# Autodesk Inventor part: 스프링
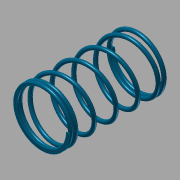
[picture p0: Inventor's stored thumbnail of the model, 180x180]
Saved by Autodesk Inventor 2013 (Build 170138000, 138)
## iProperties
Created: 2019-02
Part Number: 스프링
Material: 강철
Document SubType Name: Modeling
Designer: mduedu
Density: 2.18 g/cm^3
CustomPartVersion: 1
Author: mduedu
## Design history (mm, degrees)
sketch "경로 단면 스케치(오른쪽)"
  geometry: L1 (-7, 0.125)-(-7, -0.125); L2 (-19.793, 0)-(-17.307, 0) reference; L3 (0, -1.242)-(0, 1.242) reference; 1 further point
  constraints: 2 end point, 1 midpoint, 1 point on line, 1 vertical
  dimensions: "d0" = 0.25 distance of L1.start L1.end (= 0.25 x da_d); "d278" = 14 diameter of L1 L3 (derived)
feature "기본 곡선(오른쪽)" sketch "경로 단면 스케치(오른쪽)" dims "d2" = 5.79943 (= da_ti), "d3" = 10, "d4" = 32.5 (derived), "d5" = 0, "d6" = 90 deg, "d7" = 90 deg, "d8" = 0, "d9" = 0
sketch "주 코일 경로(오른쪽)"
node "단면 작업 평면(오른쪽)"
node "시작 작업 평면(오른쪽)"
node "끝 작업 평면(오른쪽)"
node "끝 절단 작업 평면(오른쪽)"
node "시작 절단 작업 평면(오른쪽)"
node "평면 끝 절단 작업 평면 1(오른쪽)"
node "평면 끝 절단 작업 평면 2(오른쪽)"
sketch "코일 단면 스케치(오른쪽)"
  geometry: C1 r 0.5 at (0, 0); 1 further point
  constraints: 1 centre point, 1 coincident
  dimensions: "d14" = 1 diameter of C1 (= da_d)
feature "Main Coil Feature(R)" sketch "코일 단면 스케치(오른쪽)" dims "d15" = 0, "d102" = 0 (computed from const_zero), "da_rightdir" = 10 [user parameter; used in 1 equation term]
sketch "시작 변이 코일 스케치 1(오른쪽)"
  geometry: 2 further points
  constraints: 1 horizontal alignment
feature "시작 변이 코일 1(오른쪽)" sketch "시작 변이 코일 스케치 1(오른쪽)" pitch "d16" = 4.59957 (derived); turns "d18" = 0.25 (derived); dims "d17" = 10, "d19" = 0, angle "d20" = 90 deg, angle "d21" = 90 deg, "d22" = 0, "d23" = 0, "d103" = 0 (derived), "const_zero" = 0 [user parameter; used in 2 equation terms]
sketch "Sketch  Start Transition 2(R)"
  geometry: 2 further points
  constraints: 1 horizontal alignment
feature "Coil  Start Transition 2(R)" sketch "Sketch  Start Transition 2(R)" pitch "d24" = 3.39971 (derived); turns "d26" = 0.25 (derived); dims "d25" = 10, "d27" = 0, angle "d28" = 90 deg, angle "d29" = 90 deg, "d30" = 0, "d31" = 0, "d114" = 0 (derived), "const_zero" = 0 [user parameter; used in 2 equation terms]
sketch "Sketch  Start Transition 3(R)"
  geometry: 2 further points
  constraints: 1 horizontal alignment
feature "Coil  Start Transition 3(R)" sketch "Sketch  Start Transition 3(R)" pitch "d32" = 2.19986 (derived); turns "d34" = 0.25 (derived); dims "d33" = 10, "d35" = 0, angle "d36" = 90 deg, angle "d37" = 90 deg, "d38" = 0, "d39" = 0, "d104" = 0 (derived), "const_zero" = 0 [user parameter; used in 2 equation terms]
sketch "Sketch  Start Transition 4(R)"
  geometry: 2 further points
  constraints: 1 horizontal alignment
feature "Coil  Start Transition 4(R)" sketch "Sketch  Start Transition 4(R)" pitch "d40" = 1 (derived); turns "d42" = 0.25 (derived); dims "d41" = 10, "d43" = 0, angle "d44" = 90 deg, angle "d45" = 90 deg, "d46" = 0, "d47" = 0, "d105" = 0 (derived), "const_zero" = 0 [user parameter; used in 2 equation terms]
sketch "시작 끝 스케치(오른쪽)"
  geometry: 2 further points
  constraints: 1 horizontal alignment
feature "시작 끝 코일(오른쪽)" sketch "시작 끝 스케치(오른쪽)" turns "d82" = 1.5 (derived); pitch "End_Pitch" = 1.00866 (computed from da_d, spiral_Angle); dims "d81" = 10, "d83" = 0, angle "d84" = 90 deg, angle "d85" = 90 deg, "d86" = 0, "d87" = 0, "d106" = 0 (derived), "const_zero" = 0 [user parameter; used in 2 equation terms]
sketch "시작 절단 스케치(오른쪽)"
  geometry: L1 (-14.5, -7.5)-(0.5, -7.5); L2 (0.5, -7.5)-(0.5, 7.5); L3 (0.5, 7.5)-(-14.5, 7.5); L4 (-14.5, 7.5)-(-14.5, -7.5); L5 (12.39, 0)-(-49.49, 0) reference; L6 (-7, -30.94)-(-7, 30.94) reference; 2 further points
  constraints: 8 end point, 2 midpoint, 2 parallel, 2 perpendicular, 2 point on line, 1 horizontal
  dimensions: "d99" = 15 distance of L1.start L1.end (= da_D2 + 2 x da_d)
extrude "시작 절단 피쳐(오른쪽)" cut sketch "시작 절단 스케치(오른쪽)" stored distance "d100" = 1.00866 (derived); taper "d101" = 0 deg; dims "d131" = 0 (derived), "const_zero" = 0 [user parameter; used in 2 equation terms]
sketch "끝 변이 코일 스케치 1(오른쪽)"
  geometry: 2 further points
  constraints: 1 horizontal alignment
feature "끝 변이 코일 1(오른쪽)" sketch "끝 변이 코일 스케치 1(오른쪽)" pitch "d48" = 4.59957 (derived); turns "d50" = 0.1875 (derived); dims "d49" = 10, "d51" = 0, angle "d52" = 90 deg, angle "d53" = 90 deg, "d54" = 0, "d55" = 0, "d108" = 0 (derived), "const_zero" = 0 [user parameter; used in 2 equation terms]
sketch "끝 변이 코일 스케치 2(오른쪽)"
  geometry: 2 further points
  constraints: 1 horizontal alignment
feature "끝 변이 코일 2(오른쪽)" sketch "끝 변이 코일 스케치 2(오른쪽)" pitch "d56" = 3.39971 (derived); turns "d58" = 0.1875 (derived); dims "d57" = 10, "d59" = 0, angle "d60" = 90 deg, angle "d61" = 90 deg, "d62" = 0, "d63" = 0, "d132" = 0 (derived), "const_zero" = 0 [user parameter; used in 2 equation terms]
sketch "끝 변이 코일 스케치 3(오른쪽)"
  geometry: 2 further points
  constraints: 1 horizontal alignment
feature "끝 변이 코일 3(오른쪽)" sketch "끝 변이 코일 스케치 3(오른쪽)" pitch "d64" = 2.19986 (derived); turns "d66" = 0.1875 (derived); dims "d65" = 10, "d67" = 0, angle "d68" = 90 deg, angle "d69" = 90 deg, "d70" = 0, "d71" = 0, "d133" = 0 (derived), "const_zero" = 0 [user parameter; used in 2 equation terms]
sketch "끝 변이 코일 스케치 4(오른쪽)"
  geometry: 2 further points
  constraints: 1 horizontal alignment
feature "끝 변이 코일 4(오른쪽)" sketch "끝 변이 코일 스케치 4(오른쪽)" pitch "d72" = 1 (derived); turns "d74" = 0.1875 (derived); dims "d73" = 10, "d75" = 0, angle "d76" = 90 deg, angle "d77" = 90 deg, "d78" = 0, "d79" = 0, "d134" = 0 (derived), "const_zero" = 0 [user parameter; used in 2 equation terms]
sketch "끝 코일 스케치(오른쪽)"
  geometry: 2 further points
  constraints: 1 horizontal alignment
feature "끝 코일(오른쪽)" sketch "끝 코일 스케치(오른쪽)" pitch "d88" = 1.00866 (= End_Pitch); turns "d90" = 1 (derived); dims "d89" = 10, "d91" = 0, angle "d92" = 90 deg, angle "d93" = 90 deg, "d94" = 0, "d95" = 0, "d112" = 0 (derived), "const_zero" = 0 [user parameter; used in 2 equation terms]
sketch "끝 절단 스케치(오른쪽)"
  geometry: L1 (-7.5, 0.5)-(7.5, 0.5); L2 (7.5, 0.5)-(7.5, -14.5); L3 (7.5, -14.5)-(-7.5, -14.5); L4 (-7.5, -14.5)-(-7.5, 0.5); L5 (30.94, -7)-(-30.94, -7) reference; L6 (0, -49.49)-(0, 12.39) reference; 2 further points
  constraints: 8 end point, 2 midpoint, 2 parallel, 2 perpendicular, 2 point on line, 1 horizontal
  dimensions: "d96" = 15 distance of L1.start L1.end (= da_D2 + 2 x da_d)
extrude "끝 절단 피쳐(오른쪽)" cut sketch "끝 절단 스케치(오른쪽)" stored distance "d97" = 1.00866 (derived); taper "d98" = 0 deg; dims "d113" = 0 (derived), "const_zero" = 0 [user parameter; used in 2 equation terms]
sketch "평면 끝 절단 스케치 1(오른쪽)"
  geometry: L1 (0.5, -7.5)-(-14.5, -7.5); L2 (-14.5, -7.5)-(-14.5, 7.5); L3 (-14.5, 7.5)-(0.5, 7.5); L4 (0.5, 7.5)-(0.5, -7.5); L5 (12.39, 0)-(-49.49, 0) reference; L6 (-7, -30.94)-(-7, 30.94) reference; 2 further points
  constraints: 8 end point, 2 midpoint, 2 parallel, 2 perpendicular, 2 point on line, 1 horizontal
  dimensions: "d263" = 15 distance of L3.end L1.start (derived)
extrude "평면 끝 절단 피쳐 1(오른쪽)" cut sketch "평면 끝 절단 스케치 1(오른쪽)" stored distance "d264" = 10; taper "d265" = 0 deg; dims "d266" = 10 (derived), "const_zero" = 0 [user parameter; used in 2 equation terms]
sketch "평면 끝 절단 스케치 2(오른쪽)"
  geometry: L1 (-7.5, -14.5)-(7.5, -14.5); L2 (7.5, -14.5)-(7.5, 0.5); L3 (7.5, 0.5)-(-7.5, 0.5); L4 (-7.5, 0.5)-(-7.5, -14.5); L5 (30.94, -7)-(-30.94, -7) reference; L6 (0, -49.49)-(0, 12.39) reference; 2 further points
  constraints: 8 end point, 2 midpoint, 2 parallel, 2 perpendicular, 2 point on line, 1 horizontal
  dimensions: "d259" = 15 distance of L1.start L1.end (derived)
extrude "Plain Ends Cut  2(R)" cut sketch "평면 끝 절단 스케치 2(오른쪽)" stored distance "d260" = 10; taper "d261" = 0 deg; dims "d262" = 10 (derived), "const_zero" = 0 [user parameter; used in 2 equation terms]
sketch "경로 단면 스케치(왼쪽)"
  geometry: L1 (-19.793, 0)-(-17.307, 0) reference; L2 (0, -1.242)-(0, 1.242) reference; L3 (-7, 0.125)-(-7, -0.125); 1 further point
  constraints: 2 end point, 1 midpoint, 1 perpendicular, 1 point on line
  dimensions: "d135" = 0.25 distance of L3.start L3.end (= d0); "d277" = 14 diameter of L3 L2 (derived)
feature "기본 곡선(왼쪽)" sketch "경로 단면 스케치(왼쪽)" dims "d137" = 5.79943 (= da_ti), "d138" = 10, "d139" = 32.5 (= d4), "d140" = 0, "d141" = 90 deg, "d142" = 90 deg, "d143" = 0, "d144" = 0
sketch "주 코일 경로(왼쪽)"
node "단면 작업 평면(왼쪽)"
node "시작 작업 평면(왼쪽)"
node "끝 작업 평면(왼쪽)"
node "끝 절단 작업 평면(왼쪽)"
node "시작 절단 작업 평면(왼쪽)"
node "평면 끝 절단 작업 평면 1(왼쪽)"
node "평면 끝 절단 작업 평면 2(왼쪽)"
sketch "코일 단면 스케치(왼쪽)"
  geometry: C1 r 0.5 at (0, 0); 1 further point
  constraints: 1 centre point, 1 coincident
  dimensions: "d149" = 1 diameter of C1 (= da_d)
feature "Main Coil Feature(L)" sketch "코일 단면 스케치(왼쪽)" dims "d150" = 0, "d151" = 0 (computed from const_zero), "da_rightdir" = 10 [user parameter; used in 1 equation term]
sketch "시작 변이 코일 스케치 1(왼쪽)"
  geometry: 2 further points
  constraints: 1 horizontal alignment
feature "시작 변이 코일 1(왼쪽)" sketch "시작 변이 코일 스케치 1(왼쪽)" pitch "d152" = 4.59957 (= d16); turns "d154" = 0.25 (derived); dims "d153" = 10, "d155" = 0, angle "d156" = 90 deg, angle "d157" = 90 deg, "d158" = 0, "d159" = 0, "d184" = 10 (derived), "const_zero" = 0 [user parameter; used in 2 equation terms]
sketch "시작 변이 코일 스케치 2(왼쪽)"
  geometry: 2 further points
  constraints: 1 horizontal alignment
feature "시작 변이 코일 2(왼쪽)" sketch "시작 변이 코일 스케치 2(왼쪽)" pitch "d160" = 3.39971 (= d24); turns "d162" = 0.25 (derived); dims "d161" = 10, "d163" = 0, angle "d164" = 90 deg, angle "d165" = 90 deg, "d166" = 0, "d167" = 0, "d185" = 10 (derived), "const_zero" = 0 [user parameter; used in 2 equation terms]
sketch "시작 변이 코일 스케치 3(왼쪽)"
  geometry: 2 further points
  constraints: 1 horizontal alignment
feature "시작 변이 코일 3(왼쪽)" sketch "시작 변이 코일 스케치 3(왼쪽)" pitch "d168" = 2.19986 (= d32); turns "d170" = 0.25 (derived); dims "d169" = 10, "d171" = 0, angle "d172" = 90 deg, angle "d173" = 90 deg, "d174" = 0, "d175" = 0, "d186" = 10 (derived), "const_zero" = 0 [user parameter; used in 2 equation terms]
sketch "시작 변이 코일 스케치 4(왼쪽)"
  geometry: 2 further points
  constraints: 1 horizontal alignment
feature "시작 변이 코일 4(왼쪽)" sketch "시작 변이 코일 스케치 4(왼쪽)" pitch "d176" = 1 (= d40); turns "d178" = 0.25 (derived); dims "d177" = 10, "d179" = 0, angle "d180" = 90 deg, angle "d181" = 90 deg, "d182" = 0, "d183" = 0, "d187" = 10 (derived), "const_zero" = 0 [user parameter; used in 2 equation terms]
sketch "시작 끝 스케치(왼쪽)"
  geometry: 2 further points
  constraints: 1 horizontal alignment
feature "시작 끝 코일(왼쪽)" sketch "시작 끝 스케치(왼쪽)" pitch "d188" = 1.00866 (= End_Pitch); turns "d190" = 1.5 (= d82); dims "d189" = 10, "d191" = 0, angle "d192" = 90 deg, angle "d193" = 90 deg, "d194" = 0, "d195" = 0, "d196" = 10 (derived), "const_zero" = 0 [user parameter; used in 2 equation terms]
sketch "시작 절단 스케치(왼쪽)"
  geometry: L1 (-14.5, -7.5)-(0.5, -7.5); L2 (0.5, -7.5)-(0.5, 7.5); L3 (0.5, 7.5)-(-14.5, 7.5); L4 (-14.5, 7.5)-(-14.5, -7.5); L5 (12.39, 0)-(-49.49, 0) reference; L6 (-7, -30.94)-(-7, 30.94) reference; 2 further points
  constraints: 8 end point, 2 midpoint, 2 parallel, 2 perpendicular, 2 point on line, 1 horizontal
  dimensions: "d197" = 15 distance of L1.start L1.end (= da_D2 + 2 x da_d)
extrude "시작 절단 피쳐(왼쪽)" cut sketch "시작 절단 스케치(왼쪽)" stored distance "d198" = 1.00866 (derived); taper "d199" = 0 deg; dims "d200" = 10 (derived), "const_zero" = 0 [user parameter; used in 2 equation terms]
sketch "끝 변이 코일 스케치 1(왼쪽)"
  geometry: 2 further points
  constraints: 1 horizontal alignment
feature "끝 변이 코일 1(왼쪽)" sketch "끝 변이 코일 스케치 1(왼쪽)" pitch "d201" = 4.59957 (= d16); turns "d203" = 0.1875 (derived); dims "d202" = 10, "d204" = 0, angle "d205" = 90 deg, angle "d206" = 90 deg, "d207" = 0, "d208" = 0, "d209" = 10 (derived), "const_zero" = 0 [user parameter; used in 2 equation terms]
sketch "끝 변이 코일 스케치 2(왼쪽)"
  geometry: 2 further points
  constraints: 1 horizontal alignment
feature "끝 변이 코일 2(왼쪽)" sketch "끝 변이 코일 스케치 2(왼쪽)" pitch "d210" = 3.39971 (= d24); turns "d212" = 0.1875 (derived); dims "d211" = 10, "d213" = 0, angle "d214" = 90 deg, angle "d215" = 90 deg, "d216" = 0, "d217" = 0, "d234" = 10 (derived), "const_zero" = 0 [user parameter; used in 2 equation terms]
sketch "끝 변이 코일 스케치 3(왼쪽)"
  geometry: 2 further points
  constraints: 1 horizontal alignment
feature "끝 변이 코일 3(왼쪽)" sketch "끝 변이 코일 스케치 3(왼쪽)" pitch "d218" = 2.19986 (= d32); turns "d220" = 0.1875 (derived); dims "d219" = 10, "d221" = 0, angle "d222" = 90 deg, angle "d223" = 90 deg, "d224" = 0, "d225" = 0, "d235" = 10 (derived), "const_zero" = 0 [user parameter; used in 2 equation terms]
sketch "끝 변이 코일 스케치 4(왼쪽)"
  geometry: 2 further points
  constraints: 1 horizontal alignment
feature "끝 변이 코일 4(왼쪽)" sketch "끝 변이 코일 스케치 4(왼쪽)" pitch "d226" = 1 (= d40); turns "d228" = 0.1875 (derived); dims "d227" = 10, "d229" = 0, angle "d230" = 90 deg, angle "d231" = 90 deg, "d232" = 0, "d233" = 0, "d236" = 10 (derived), "const_zero" = 0 [user parameter; used in 2 equation terms]
sketch "끝 코일 스케치(왼쪽)"
  geometry: 2 further points
  constraints: 1 horizontal alignment
feature "끝 코일(왼쪽)" sketch "끝 코일 스케치(왼쪽)" pitch "d237" = 1.00866 (computed from da_d, spiral_Angle); turns "d239" = 1 (= d90); dims "d238" = 10, "d240" = 0, angle "d241" = 90 deg, angle "d242" = 90 deg, "d243" = 0, "d244" = 0, "d248" = 10 (derived), "const_zero" = 0 [user parameter; used in 2 equation terms]
sketch "끝 절단 스케치(왼쪽)"
  geometry: L1 (-7.5, -0.5)-(7.5, -0.5); L2 (7.5, -0.5)-(7.5, 14.5); L3 (7.5, 14.5)-(-7.5, 14.5); L4 (-7.5, 14.5)-(-7.5, -0.5); L5 (30.94, 7)-(-30.94, 7) reference; L6 (0, -12.39)-(0, 49.49) reference; 2 further points
  constraints: 8 end point, 2 midpoint, 2 parallel, 2 perpendicular, 2 point on line, 1 horizontal
  dimensions: "d245" = 15 distance of L1.end L2.end (derived)
extrude "끝 절단 피쳐(왼쪽)" cut sketch "끝 절단 스케치(왼쪽)" stored distance "d246" = 1.00866 (derived); taper "d247" = 0 deg; dims "d249" = 10 (derived), "const_zero" = 0 [user parameter; used in 2 equation terms]
sketch "평면 끝 절단 스케치 1(왼쪽)"
  geometry: L1 (0.5, -7.5)-(-14.5, -7.5); L2 (-14.5, -7.5)-(-14.5, 7.5); L3 (-14.5, 7.5)-(0.5, 7.5); L4 (0.5, 7.5)-(0.5, -7.5); L5 (-14.5, -7.5)-(0.5, 7.5); 2 further points
  constraints: 10 end point, 2 parallel, 2 perpendicular, 1 coincident, 1 horizontal, 1 midpoint
  dimensions: "d272" = 15 distance of L3.end L1.start (derived)
extrude "Cut Plain Ends Cut 1(L)" cut sketch "평면 끝 절단 스케치 1(왼쪽)" stored distance "d273" = 10; taper "d274" = 0 deg; dims "d275" = 20 (derived), "const_zero" = 0 [user parameter; used in 2 equation terms]
sketch "평면 끝 절단 스케치 2(왼쪽)"
  geometry: L1 (-8.802, -0.5)-(8.802, -0.5); L2 (8.802, -0.5)-(8.802, 14.5); L3 (8.802, 14.5)-(-8.802, 14.5); L4 (-8.802, 14.5)-(-8.802, -0.5); L5 (36.313, 7)-(-36.313, 7) reference; L6 (0, -12.39)-(0, 49.49) reference; 2 further points
  constraints: 8 end point, 2 midpoint, 2 parallel, 2 point on line, 1 horizontal, 1 perpendicular
  dimensions: "d254" = 15 distance of L1.end L2.end (derived)
extrude "Cut Plain Ends Cut 2(L)" cut sketch "평면 끝 절단 스케치 2(왼쪽)" stored distance "d255" = 10; taper "d256" = 0 deg; dims "d257" = 20 (derived), "const_zero" = 0 [user parameter; used in 2 equation terms]
node "iMate 기반 작업 평면"
node "중심점 미리보기"
node "x축 미리보기"
  node "작업 평면 시작 단면"
node "조립기준평면"
body "Solid1"
body "Srf1"
body "Srf2"
other parameters: "da_d" = 1 [user parameter; used in 8 equation terms], "da_D2" = 13 [user parameter; used in 3 equation terms], "da_ti" = 5.79943 [user parameter; used in 2 equation terms], "da_nz1" = 15 [user parameter], "spiral_Angle" = 1.31102 [user parameter; used in 2 equation terms], "d12" = 3.09988 (derived), "d13" = -4.05199 (derived), "Not_rightdir" = 0 (computed from da_rightdir) [user parameter], "d121" = 0.26078 (derived), "d145" = 3.09988 (= d12), "d146" = -4.05199 (= d13), "d147" = 0.26078 (= d121), "d148" = 0.00862 (derived), "d258" = -0.00862 (derived), "d267" = 0, "d270" = -3.92699 (derived), "d271" = 0, "da_nt2" = 7.5 [user parameter], "startTransitionCoil" = 2.5 [user parameter], "endTransitionCoil" = 1.875 [user parameter], "da_zo1" = 7.5 [user parameter], "da_zo2" = 5 [user parameter], "cutHeightStart" = 0.75649 [user parameter], "cutHeightEnd" = 0.50433 [user parameter], "Not_startClose" = 0 [user parameter], "Not_endClose" = 0 [user parameter], "Not_startGround" = 0 [user parameter], "Not_endGround" = 0 [user parameter], "d276" = -157.07963 (derived), "d279" = 0
